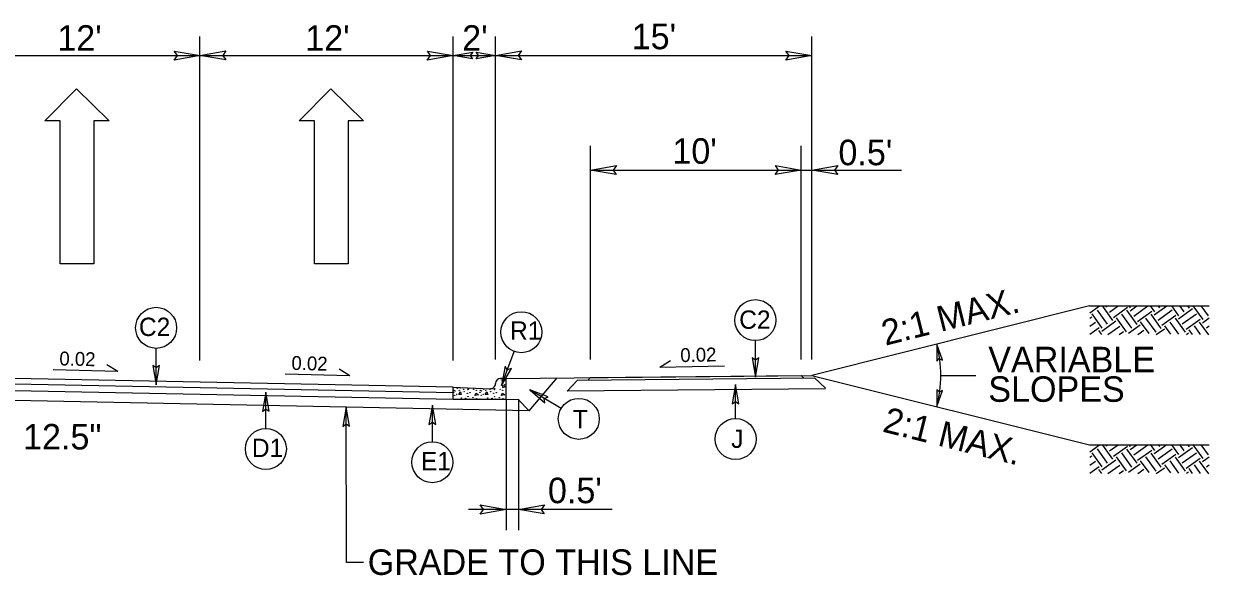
# Model space of a CAD drawing. Extents: x 3025871 to 3026431, y 707165 to 707825.
# Drawn here: x 3026374.6 to 3026430.8, y 707593.8 to 707619.9 of the extents above; entities that cross this region are included whole.
import ezdxf

# ---------------------------------------------------------------- set-up
doc = ezdxf.new("R2010")
doc.units = 0
for name, color, linetype in [('Prop Drainage Structure Junction Box with Manhole CELL', 7, 'Continuous'), ('Prop Drainage Structure Junction Box with Slab Lid TB 840 34 CELL', 7, 'Continuous'), ('Prop Drainage Structure Plot Symbol 50 Scale', 7, 'Continuous'), ('Prop Pavement Schedule Description CELL', 7, 'Continuous'), ('Sheet Data Field CELL', 7, 'Continuous'), ('Sheet Plot Border Inside CELL', 7, 'Continuous'), ('Sheet Sticker Incomplete CELL', 7, 'Continuous'), ('Sheet Typical CELL', 7, 'Continuous'), ('Typical Arrow Superelevation CELL', 7, 'Continuous'), ('Typical Grade Point Symbol CELL', 7, 'Continuous'), ('Typical Text Centerline CELL', 7, 'Continuous'), ('Typical Text Grade Point CELL', 7, 'Continuous')]:
    doc.layers.add(name, color=color, linetype=linetype)

msp = doc.modelspace()

# ---------------------------------------------------------------- linework, layer by layer
at = {"layer": 'Prop Drainage Structure Junction Box with Manhole CELL'}
msp.add_line((3026398.531, 707601.603), (3026368.422, 707602.206), dxfattribs=at)
at = {"layer": 'Prop Drainage Structure Junction Box with Slab Lid TB 840 34 CELL'}
for p, q in [((3026382.912, 707603.988), (3026382.912, 707619.333)), ((3026394.92, 707603.988), (3026394.92, 707619.333)), ((3026396.929, 707604.029), (3026396.929, 707619.333)), ((3026411.929, 707604.029), (3026411.929, 707619.333)), ((3026327.902, 707618.441), (3026394.92, 707618.441)), ((3026394.92, 707618.441), (3026411.929, 707618.441)), ((3026401.429, 707604.029), (3026401.429, 707614.159)), ((3026411.429, 707604.029), (3026411.429, 707614.159)), ((3026401.429, 707613.011), (3026416.186, 707613.011)), ((3026418.044, 707603.278), (3026419.7, 707603.278)), ((3026397.429, 707602.132), (3026397.429, 707595.934)), ((3026398.014, 707602.144), (3026398.014, 707595.934)), ((3026402.462, 707596.924), (3026395.642, 707596.924)), ((3026390.664, 707594.41), (3026389.854, 707594.41))]:
    msp.add_line(p, q, dxfattribs=at)
msp.add_arc((3026411.929, 707603.278), 6.116, 345.9638, 14.0362, dxfattribs=at)
at = {"layer": 'Prop Drainage Structure Plot Symbol 50 Scale'}
for p, q in [((3026396.927, 707602.885), (3026396.927, 707602.895)), ((3026397.429, 707603.136), (3026397.168, 707603.136)), ((3026397.429, 707602.132), (3026397.429, 707603.136)), ((3026394.92, 707602.132), (3026394.92, 707602.717)), ((3026394.92, 707602.717), (3026396.677, 707602.644)), ((3026395.182, 707602.373), (3026395.269, 707602.493)), ((3026395.303, 707602.379), (3026395.182, 707602.373)), ((3026395.269, 707602.493), (3026395.303, 707602.379)), ((3026395.95, 707602.321), (3026396.013, 707602.436)), ((3026396.116, 707602.361), (3026395.95, 707602.321)), ((3026396.013, 707602.436), (3026396.116, 707602.361)), ((3026396.436, 707602.373), (3026396.522, 707602.493)), ((3026396.556, 707602.379), (3026396.436, 707602.373)), ((3026396.522, 707602.493), (3026396.556, 707602.379)), ((3026397.203, 707602.321), (3026397.266, 707602.436)), ((3026397.37, 707602.361), (3026397.203, 707602.321)), ((3026397.238, 707602.801), (3026397.255, 707602.71)), ((3026397.393, 707602.756), (3026397.238, 707602.801)), ((3026397.255, 707602.71), (3026397.393, 707602.756)), ((3026397.266, 707602.436), (3026397.37, 707602.361)), ((3026397.429, 707602.132), (3026394.92, 707602.132))]:
    msp.add_line(p, q, dxfattribs=at)
for centre in [(3026397.198, 707603.06), (3026397.416, 707603.025), (3026394.937, 707602.47), (3026394.954, 707602.568), (3026394.994, 707602.327), (3026395.01, 707602.533), (3026395.091, 707602.373), (3026395.119, 707602.659), (3026395.217, 707602.573), (3026395.263, 707602.676), (3026395.412, 707602.613), (3026395.44, 707602.511), (3026395.589, 707602.425), (3026395.618, 707602.597), (3026395.635, 707602.647), (3026395.715, 707602.453), (3026395.893, 707602.619), (3026396.013, 707602.568), (3026396.191, 707602.47), (3026396.208, 707602.568), (3026396.248, 707602.327), (3026396.264, 707602.533), (3026396.344, 707602.373), (3026396.373, 707602.616), (3026396.47, 707602.573), (3026396.665, 707602.613), (3026396.694, 707602.511), (3026396.843, 707602.425), (3026396.871, 707602.597), (3026396.889, 707602.647), (3026396.969, 707602.453), (3026397.146, 707602.619), (3026397.267, 707602.568), (3026397.364, 707602.842), (3026394.931, 707602.161), (3026395.142, 707602.138), (3026395.303, 707602.207), (3026395.509, 707602.184), (3026395.623, 707602.27), (3026395.681, 707602.155), (3026395.858, 707602.218), (3026396.03, 707602.178), (3026396.185, 707602.161), (3026396.396, 707602.138), (3026396.556, 707602.207), (3026396.763, 707602.184), (3026396.877, 707602.27), (3026396.934, 707602.155), (3026397.112, 707602.218), (3026397.284, 707602.178)]:
    msp.add_circle(centre, 0.00805, dxfattribs=at)
for centre, start, end in [((3026396.687, 707602.885), 267.6155, 0), ((3026397.168, 707602.895), 90, 180)]:
    msp.add_arc(centre, 0.24, start, end, dxfattribs=at)
at = {"layer": 'Prop Pavement Schedule Description CELL'}
for p, q in [((3026394.92, 707602.717), (3026370.912, 707603.198)), ((3026370.913, 707602.948), (3026394.92, 707602.467)), ((3026400.812, 707603.044), (3026400.322, 707602.534)), ((3026400.812, 707603.044), (3026412.062, 707603.154)), ((3026401.429, 707603.175), (3026401.307, 707603.049)), ((3026401.429, 707603.175), (3026411.429, 707603.273)), ((3026411.429, 707603.273), (3026411.557, 707603.149)), ((3026412.057, 707603.159), (3026412.572, 707602.664)), ((3026394.921, 707602.134), (3026370.916, 707602.614)), ((3026400.327, 707602.539), (3026412.577, 707602.659))]:
    msp.add_line(p, q, dxfattribs=at)
at = {"layer": 'Sheet Data Field CELL'}
for p, q in [((3026375.555, 707615.338), (3026377.054, 707616.862)), ((3026377.054, 707616.862), (3026378.601, 707615.338)), ((3026387.614, 707615.338), (3026389.113, 707616.862)), ((3026389.113, 707616.862), (3026390.66, 707615.338)), ((3026376.28, 707615.338), (3026375.555, 707615.338)), ((3026376.28, 707608.568), (3026376.28, 707615.338)), ((3026378.601, 707615.338), (3026377.876, 707615.338)), ((3026377.876, 707615.338), (3026377.876, 707608.568)), ((3026388.339, 707615.338), (3026387.614, 707615.338)), ((3026388.339, 707608.568), (3026388.339, 707615.338)), ((3026390.66, 707615.338), (3026389.935, 707615.338)), ((3026389.935, 707615.338), (3026389.935, 707608.568)), ((3026377.876, 707608.568), (3026376.28, 707608.568)), ((3026389.935, 707608.568), (3026388.339, 707608.568))]:
    msp.add_line(p, q, dxfattribs=at)
at = {"layer": 'Sheet Plot Border Inside CELL'}
msp.add_line((3026398.014, 707602.12), (3026397.429, 707602.132), dxfattribs=at)
at = {"layer": 'Sheet Sticker Incomplete CELL'}
for p, q in [((3026404.716, 707603.67), (3026405.232, 707603.982)), ((3026379.015, 707603.465), (3026375.947, 707603.542)), ((3026379.015, 707603.465), (3026378.501, 707603.779)), ((3026390.019, 707603.254), (3026389.506, 707603.568)), ((3026404.716, 707603.67), (3026407.784, 707603.732)), ((3026390.019, 707603.254), (3026386.952, 707603.33))]:
    msp.add_line(p, q, dxfattribs=at)
at = {"layer": 'Sheet Typical CELL'}
for p, q in [((3026397.429, 707603.136), (3026411.929, 707603.278)), ((3026398.531, 707601.603), (3026399.854, 707603.159)), ((3026398.014, 707602.12), (3026398.531, 707601.603))]:
    msp.add_line(p, q, dxfattribs=at)
at = {"layer": 'Typical Grade Point Symbol CELL'}
for p, q in [((3026380.834, 707602.835), (3026380.833, 707604.559)), ((3026409.254, 707603.199), (3026409.253, 707604.923)), ((3026397.206, 707602.801), (3026397.813, 707604.415)), ((3026386.035, 707600.76), (3026386.034, 707602.485)), ((3026400.04, 707601.712), (3026398.555, 707602.588)), ((3026408.314, 707601.23), (3026408.313, 707602.845)), ((3026389.854, 707594.41), (3026389.849, 707601.777)), ((3026393.933, 707600.135), (3026393.932, 707601.86))]:
    msp.add_line(p, q, dxfattribs=at)
for centre in [(3026409.253, 707605.895), (3026380.833, 707605.531), (3026398.155, 707605.325), (3026400.877, 707601.217), (3026408.314, 707600.258), (3026386.035, 707599.788), (3026393.933, 707599.163)]:
    msp.add_circle(centre, 0.972, dxfattribs=at)
at = {"layer": 'Typical Text Centerline CELL'}
for points in [[(3026381.688, 707618.652), (3026382.913, 707618.441), (3026381.681, 707618.223), (3026381.838, 707618.441)], [(3026384.138, 707618.23), (3026382.912, 707618.441), (3026384.144, 707618.659), (3026383.988, 707618.441)], [(3026393.696, 707618.652), (3026394.921, 707618.441), (3026393.689, 707618.223), (3026393.846, 707618.441)], [(3026395.839, 707618.283), (3026394.92, 707618.441), (3026395.844, 707618.604), (3026395.727, 707618.441)], [(3026396.01, 707618.599), (3026396.929, 707618.441), (3026396.005, 707618.278), (3026396.123, 707618.441)], [(3026398.154, 707618.23), (3026396.929, 707618.441), (3026398.16, 707618.659), (3026398.004, 707618.441)], [(3026410.703, 707618.652), (3026411.929, 707618.441), (3026410.697, 707618.223), (3026410.853, 707618.441)], [(3026402.654, 707612.8), (3026401.429, 707613.011), (3026402.66, 707613.228), (3026402.504, 707613.011)], [(3026410.203, 707613.222), (3026411.429, 707613.011), (3026410.197, 707612.793), (3026410.353, 707613.011)], [(3026413.154, 707612.8), (3026411.929, 707613.011), (3026413.16, 707613.228), (3026413.004, 707613.011)], [(3026418.125, 707604.004), (3026417.861, 707604.761), (3026417.853, 707603.955), (3026417.975, 707604.077)], [(3026409.097, 707604.108), (3026409.254, 707603.199), (3026409.415, 707604.114), (3026409.253, 707603.997)], [(3026380.677, 707603.744), (3026380.834, 707602.835), (3026380.995, 707603.75), (3026380.834, 707603.633)], [(3026397.379, 707603.707), (3026397.206, 707602.801), (3026397.679, 707603.6), (3026397.487, 707603.548)], [(3026386.191, 707601.575), (3026386.034, 707602.485), (3026385.873, 707601.57), (3026386.034, 707601.686)], [(3026399.418, 707602.261), (3026398.555, 707602.588), (3026399.26, 707601.984), (3026399.242, 707602.182)], [(3026408.47, 707601.936), (3026408.313, 707602.845), (3026408.152, 707601.931), (3026408.313, 707602.047)], [(3026417.858, 707602.596), (3026417.861, 707601.795), (3026418.131, 707602.555), (3026417.976, 707602.479)], [(3026390.006, 707600.868), (3026389.849, 707601.777), (3026389.688, 707600.862), (3026389.85, 707600.979)], [(3026394.089, 707600.95), (3026393.932, 707601.86), (3026393.771, 707600.945), (3026393.932, 707601.062)], [(3026396.205, 707597.135), (3026397.43, 707596.924), (3026396.198, 707596.706), (3026396.355, 707596.924)], [(3026399.239, 707596.713), (3026398.014, 707596.924), (3026399.246, 707597.142), (3026399.09, 707596.924)]]:
    msp.add_lwpolyline(points, close=True, dxfattribs=at)
at = {"layer": 'Typical Text Grade Point CELL'}
for p, q in [((3026425.094, 707606.569), (3026411.929, 707603.278)), ((3026425.094, 707606.569), (3026430.778, 707606.569)), ((3026425.094, 707606.569), (3026430.778, 707606.569)), ((3026425.115, 707606.24), (3026425.575, 707606.57)), ((3026425.115, 707606.24), (3026425.575, 707606.57)), ((3026425.955, 707605.703), (3026425.475, 707606.371)), ((3026425.955, 707605.703), (3026425.475, 707606.371)), ((3026426.206, 707605.883), (3026425.725, 707606.551)), ((3026426.206, 707605.883), (3026425.725, 707606.551)), ((3026425.869, 707606.528), (3026425.929, 707606.571)), ((3026425.869, 707606.528), (3026425.929, 707606.571)), ((3026426.049, 707606.277), (3026426.46, 707606.573)), ((3026426.049, 707606.277), (3026426.46, 707606.573)), ((3026426.229, 707606.027), (3026426.898, 707606.507)), ((3026426.229, 707606.027), (3026426.898, 707606.507)), ((3026427.354, 707605.695), (3026426.874, 707606.363)), ((3026427.354, 707605.695), (3026426.874, 707606.363)), ((3026427.041, 707606.483), (3026426.976, 707606.574)), ((3026427.041, 707606.483), (3026426.976, 707606.574)), ((3026427.018, 707606.34), (3026427.345, 707606.575)), ((3026427.018, 707606.34), (3026427.345, 707606.575)), ((3026427.198, 707606.089), (3026427.866, 707606.57)), ((3026427.198, 707606.089), (3026427.866, 707606.57)), ((3026427.378, 707605.839), (3026428.046, 707606.319)), ((3026427.378, 707605.839), (3026428.046, 707606.319)), ((3026428.19, 707606.295), (3026427.987, 707606.577)), ((3026428.19, 707606.295), (3026427.987, 707606.577)), ((3026428.166, 707606.152), (3026428.761, 707606.579)), ((3026428.166, 707606.152), (3026428.761, 707606.579)), ((3026428.346, 707605.901), (3026429.015, 707606.381)), ((3026428.346, 707605.901), (3026429.015, 707606.381)), ((3026428.44, 707606.475), (3026428.367, 707606.578)), ((3026428.44, 707606.475), (3026428.367, 707606.578)), ((3026429.339, 707606.107), (3026429.007, 707606.569)), ((3026429.339, 707606.107), (3026429.007, 707606.569)), ((3026429.315, 707605.964), (3026429.983, 707606.444)), ((3026429.315, 707605.964), (3026429.983, 707606.444)), ((3026429.589, 707606.287), (3026429.378, 707606.581)), ((3026429.589, 707606.287), (3026429.378, 707606.581)), ((3026429.84, 707606.468), (3026429.767, 707606.569)), ((3026429.84, 707606.468), (3026429.767, 707606.569)), ((3026430.487, 707605.919), (3026430.02, 707606.569)), ((3026430.487, 707605.919), (3026430.02, 707606.569)), ((3026430.738, 707606.099), (3026430.4, 707606.569)), ((3026430.738, 707606.099), (3026430.4, 707606.569)), ((3026425.115, 707605.986), (3026425.2, 707606.048)), ((3026425.115, 707605.986), (3026425.2, 707606.048)), ((3026425.115, 707605.606), (3026425.381, 707605.797)), ((3026425.115, 707605.606), (3026425.381, 707605.797)), ((3026425.704, 707605.523), (3026425.224, 707606.191)), ((3026425.704, 707605.523), (3026425.224, 707606.191)), ((3026425.681, 707605.379), (3026426.349, 707605.86)), ((3026425.681, 707605.379), (3026426.349, 707605.86)), ((3026426.853, 707605.335), (3026426.373, 707606.003)), ((3026426.853, 707605.335), (3026426.373, 707606.003)), ((3026427.104, 707605.515), (3026426.623, 707606.183)), ((3026427.104, 707605.515), (3026426.623, 707606.183)), ((3026426.949, 707605.277), (3026427.498, 707605.671)), ((3026426.949, 707605.277), (3026427.498, 707605.671)), ((3026427.922, 707605.257), (3026427.521, 707605.815)), ((3026427.922, 707605.257), (3026427.521, 707605.815)), ((3026428.252, 707605.327), (3026427.772, 707605.995)), ((3026428.252, 707605.327), (3026427.772, 707605.995)), ((3026428.503, 707605.507), (3026428.023, 707606.175)), ((3026428.503, 707605.507), (3026428.023, 707606.175)), ((3026428.527, 707605.65), (3026429.195, 707606.131)), ((3026428.527, 707605.65), (3026429.195, 707606.131)), ((3026429.336, 707605.229), (3026428.921, 707605.807)), ((3026429.336, 707605.229), (3026428.921, 707605.807)), ((3026429.652, 707605.319), (3026429.171, 707605.987)), ((3026429.652, 707605.319), (3026429.171, 707605.987)), ((3026429.495, 707605.713), (3026430.164, 707606.193)), ((3026429.495, 707605.713), (3026430.164, 707606.193)), ((3026429.675, 707605.462), (3026430.344, 707605.943)), ((3026429.675, 707605.462), (3026430.344, 707605.943)), ((3026430.75, 707605.201), (3026430.32, 707605.799)), ((3026430.75, 707605.201), (3026430.32, 707605.799)), ((3026430.464, 707605.776), (3026430.778, 707606.002)), ((3026430.464, 707605.776), (3026430.778, 707606.002)), ((3026425.115, 707605.226), (3026425.561, 707605.546)), ((3026425.115, 707605.226), (3026425.561, 707605.546)), ((3026425.676, 707605.209), (3026425.537, 707605.403)), ((3026425.676, 707605.209), (3026425.537, 707605.403)), ((3026425.973, 707605.209), (3026426.529, 707605.609)), ((3026425.973, 707605.209), (3026426.529, 707605.609)), ((3026426.502, 707605.209), (3026426.709, 707605.358)), ((3026426.502, 707605.209), (3026426.709, 707605.358)), ((3026427.383, 707605.209), (3026427.678, 707605.421)), ((3026427.383, 707605.209), (3026427.678, 707605.421)), ((3026428.265, 707605.209), (3026428.647, 707605.483)), ((3026428.265, 707605.209), (3026428.647, 707605.483)), ((3026428.951, 707605.237), (3026428.67, 707605.627)), ((3026428.951, 707605.237), (3026428.67, 707605.627)), ((3026429.693, 707605.222), (3026429.795, 707605.295)), ((3026429.693, 707605.222), (3026429.795, 707605.295)), ((3026429.979, 707605.216), (3026429.819, 707605.439)), ((3026429.979, 707605.216), (3026429.819, 707605.439)), ((3026430.365, 707605.208), (3026430.07, 707605.619)), ((3026430.365, 707605.208), (3026430.07, 707605.619)), ((3026430.644, 707605.525), (3026430.778, 707605.622)), ((3026430.644, 707605.525), (3026430.778, 707605.622)), ((3026411.929, 707603.278), (3026425.094, 707599.987)), ((3026425.094, 707599.987), (3026430.778, 707599.987)), ((3026425.094, 707599.987), (3026430.778, 707599.987)), ((3026425.115, 707599.657), (3026425.575, 707599.988)), ((3026425.115, 707599.657), (3026425.575, 707599.988)), ((3026425.704, 707598.94), (3026425.224, 707599.609)), ((3026425.704, 707598.94), (3026425.224, 707599.609)), ((3026425.955, 707599.12), (3026425.475, 707599.789)), ((3026425.955, 707599.12), (3026425.475, 707599.789)), ((3026426.206, 707599.3), (3026425.725, 707599.969)), ((3026426.206, 707599.3), (3026425.725, 707599.969)), ((3026425.869, 707599.945), (3026425.929, 707599.989)), ((3026425.869, 707599.945), (3026425.929, 707599.989)), ((3026426.049, 707599.695), (3026426.46, 707599.99)), ((3026426.049, 707599.695), (3026426.46, 707599.99)), ((3026426.229, 707599.444), (3026426.898, 707599.924)), ((3026426.229, 707599.444), (3026426.898, 707599.924)), ((3026427.104, 707598.932), (3026426.623, 707599.601)), ((3026427.104, 707598.932), (3026426.623, 707599.601)), ((3026427.354, 707599.112), (3026426.874, 707599.781)), ((3026427.354, 707599.112), (3026426.874, 707599.781)), ((3026427.041, 707599.901), (3026426.976, 707599.992)), ((3026427.041, 707599.901), (3026426.976, 707599.992)), ((3026427.018, 707599.757), (3026427.345, 707599.993)), ((3026427.018, 707599.757), (3026427.345, 707599.993)), ((3026427.198, 707599.507), (3026427.866, 707599.987)), ((3026427.198, 707599.507), (3026427.866, 707599.987)), ((3026427.378, 707599.256), (3026428.046, 707599.736)), ((3026427.378, 707599.256), (3026428.046, 707599.736)), ((3026428.19, 707599.713), (3026427.987, 707599.995)), ((3026428.19, 707599.713), (3026427.987, 707599.995)), ((3026428.503, 707598.924), (3026428.023, 707599.593)), ((3026428.503, 707598.924), (3026428.023, 707599.593)), ((3026428.166, 707599.569), (3026428.761, 707599.997)), ((3026428.166, 707599.569), (3026428.761, 707599.997)), ((3026428.346, 707599.319), (3026429.015, 707599.799)), ((3026428.346, 707599.319), (3026429.015, 707599.799)), ((3026428.44, 707599.893), (3026428.367, 707599.996)), ((3026428.44, 707599.893), (3026428.367, 707599.996)), ((3026428.527, 707599.068), (3026429.195, 707599.548)), ((3026428.527, 707599.068), (3026429.195, 707599.548)), ((3026429.339, 707599.525), (3026429.007, 707599.987)), ((3026429.339, 707599.525), (3026429.007, 707599.987)), ((3026429.315, 707599.381), (3026429.983, 707599.861)), ((3026429.315, 707599.381), (3026429.983, 707599.861)), ((3026429.589, 707599.705), (3026429.378, 707599.999)), ((3026429.589, 707599.705), (3026429.378, 707599.999)), ((3026429.495, 707599.13), (3026430.164, 707599.611)), ((3026429.495, 707599.13), (3026430.164, 707599.611)), ((3026429.84, 707599.885), (3026429.767, 707599.987)), ((3026429.84, 707599.885), (3026429.767, 707599.987)), ((3026430.487, 707599.337), (3026430.02, 707599.987)), ((3026430.487, 707599.337), (3026430.02, 707599.987)), ((3026430.738, 707599.517), (3026430.4, 707599.987)), ((3026430.738, 707599.517), (3026430.4, 707599.987)), ((3026425.115, 707599.404), (3026425.2, 707599.465)), ((3026425.115, 707599.404), (3026425.2, 707599.465)), ((3026425.115, 707599.024), (3026425.381, 707599.214)), ((3026425.115, 707599.024), (3026425.381, 707599.214)), ((3026425.115, 707598.644), (3026425.561, 707598.964)), ((3026425.115, 707598.644), (3026425.561, 707598.964)), ((3026425.681, 707598.797), (3026426.349, 707599.277)), ((3026425.681, 707598.797), (3026426.349, 707599.277)), ((3026425.973, 707598.627), (3026426.529, 707599.026)), ((3026425.973, 707598.627), (3026426.529, 707599.026)), ((3026426.853, 707598.752), (3026426.373, 707599.421)), ((3026426.853, 707598.752), (3026426.373, 707599.421)), ((3026426.949, 707598.694), (3026427.498, 707599.089)), ((3026426.949, 707598.694), (3026427.498, 707599.089)), ((3026427.922, 707598.675), (3026427.521, 707599.232)), ((3026427.922, 707598.675), (3026427.521, 707599.232)), ((3026428.252, 707598.744), (3026427.772, 707599.413)), ((3026428.252, 707598.744), (3026427.772, 707599.413)), ((3026428.951, 707598.654), (3026428.67, 707599.044)), ((3026428.951, 707598.654), (3026428.67, 707599.044)), ((3026429.336, 707598.646), (3026428.921, 707599.225)), ((3026429.336, 707598.646), (3026428.921, 707599.225)), ((3026429.652, 707598.736), (3026429.171, 707599.405)), ((3026429.652, 707598.736), (3026429.171, 707599.405)), ((3026429.675, 707598.88), (3026430.344, 707599.36)), ((3026429.675, 707598.88), (3026430.344, 707599.36)), ((3026430.365, 707598.626), (3026430.07, 707599.036)), ((3026430.365, 707598.626), (3026430.07, 707599.036)), ((3026430.75, 707598.618), (3026430.32, 707599.217)), ((3026430.75, 707598.618), (3026430.32, 707599.217)), ((3026430.464, 707599.193), (3026430.778, 707599.419)), ((3026430.464, 707599.193), (3026430.778, 707599.419)), ((3026430.644, 707598.942), (3026430.778, 707599.039)), ((3026430.644, 707598.942), (3026430.778, 707599.039)), ((3026425.676, 707598.627), (3026425.537, 707598.82)), ((3026425.676, 707598.627), (3026425.537, 707598.82)), ((3026426.502, 707598.627), (3026426.709, 707598.776)), ((3026426.502, 707598.627), (3026426.709, 707598.776)), ((3026427.383, 707598.627), (3026427.678, 707598.838)), ((3026427.383, 707598.627), (3026427.678, 707598.838)), ((3026428.265, 707598.627), (3026428.647, 707598.901)), ((3026428.265, 707598.627), (3026428.647, 707598.901)), ((3026429.693, 707598.639), (3026429.795, 707598.713)), ((3026429.693, 707598.639), (3026429.795, 707598.713)), ((3026429.979, 707598.634), (3026429.819, 707598.856)), ((3026429.979, 707598.634), (3026429.819, 707598.856))]:
    msp.add_line(p, q, dxfattribs=at)

# ---------------------------------------------------------------- texts
at = {"layer": 'Prop Drainage Structure Junction Box with Slab Lid TB 840 34 CELL'}
for s, height, p in [("12'", 1.2089, (3026376.145, 707618.667)), ("12'", 1.2089, (3026387.903, 707618.667)), ("2'", 1.2089, (3026395.348, 707618.667)), ("15'", 1.2089, (3026403.386, 707618.737)), ("10'", 1.2089, (3026405.315, 707613.307)), ("0.5'", 1.2089, (3026413.19, 707613.239)), ('12.5"', 1.2089, (3026374.521, 707599.765)), ("0.5'", 1.2089, (3026399.414, 707597.219)), ('GRADE TO THIS LINE', 1.20892, (3026390.866, 707593.82))]:
    msp.add_text(s, height=height, dxfattribs=at).set_placement(p)
at = {"layer": 'Sheet Sticker Incomplete CELL'}
for s, rotation, p in [('0.02 ', 1.2029, (3026405.697, 707603.906)), ('0.02', 358.5679, (3026376.237, 707603.752)), ('0.02', 358.5679, (3026387.242, 707603.541))]:
    msp.add_text(s, height=0.6583, rotation=rotation, dxfattribs=at).set_placement(p)
at = {"layer": 'Typical Arrow Superelevation CELL'}
for s, p in [('C2', (3026408.484, 707605.485)), ('C2', (3026380.016, 707605.143)), ('J', (3026408.104, 707599.839)), ('D1', (3026385.372, 707599.405)), ('E1', (3026393.388, 707598.78))]:
    msp.add_text(s, height=0.87, dxfattribs=at).set_placement(p)
for s, p in [('R1', (3026397.617, 707604.967)), ('T', (3026400.593, 707600.766))]:
    msp.add_text(s, height=0.87, rotation=360, dxfattribs=at).set_placement(p)
at = {"layer": 'Typical Text Grade Point CELL'}
for rotation, p in [(14.0362, (3026415.415, 707604.68)), (345.9638, (3026415.236, 707600.62))]:
    msp.add_text('2:1 MAX.', height=1.2089, rotation=rotation, dxfattribs=at).set_placement(p)
for s, p in [('VARIABLE', (3026420.298, 707603.426)), ('SLOPES', (3026420.298, 707602.024))]:
    msp.add_text(s, height=1.2089, dxfattribs=at).set_placement(p)

doc.saveas('drawing.dxf')
